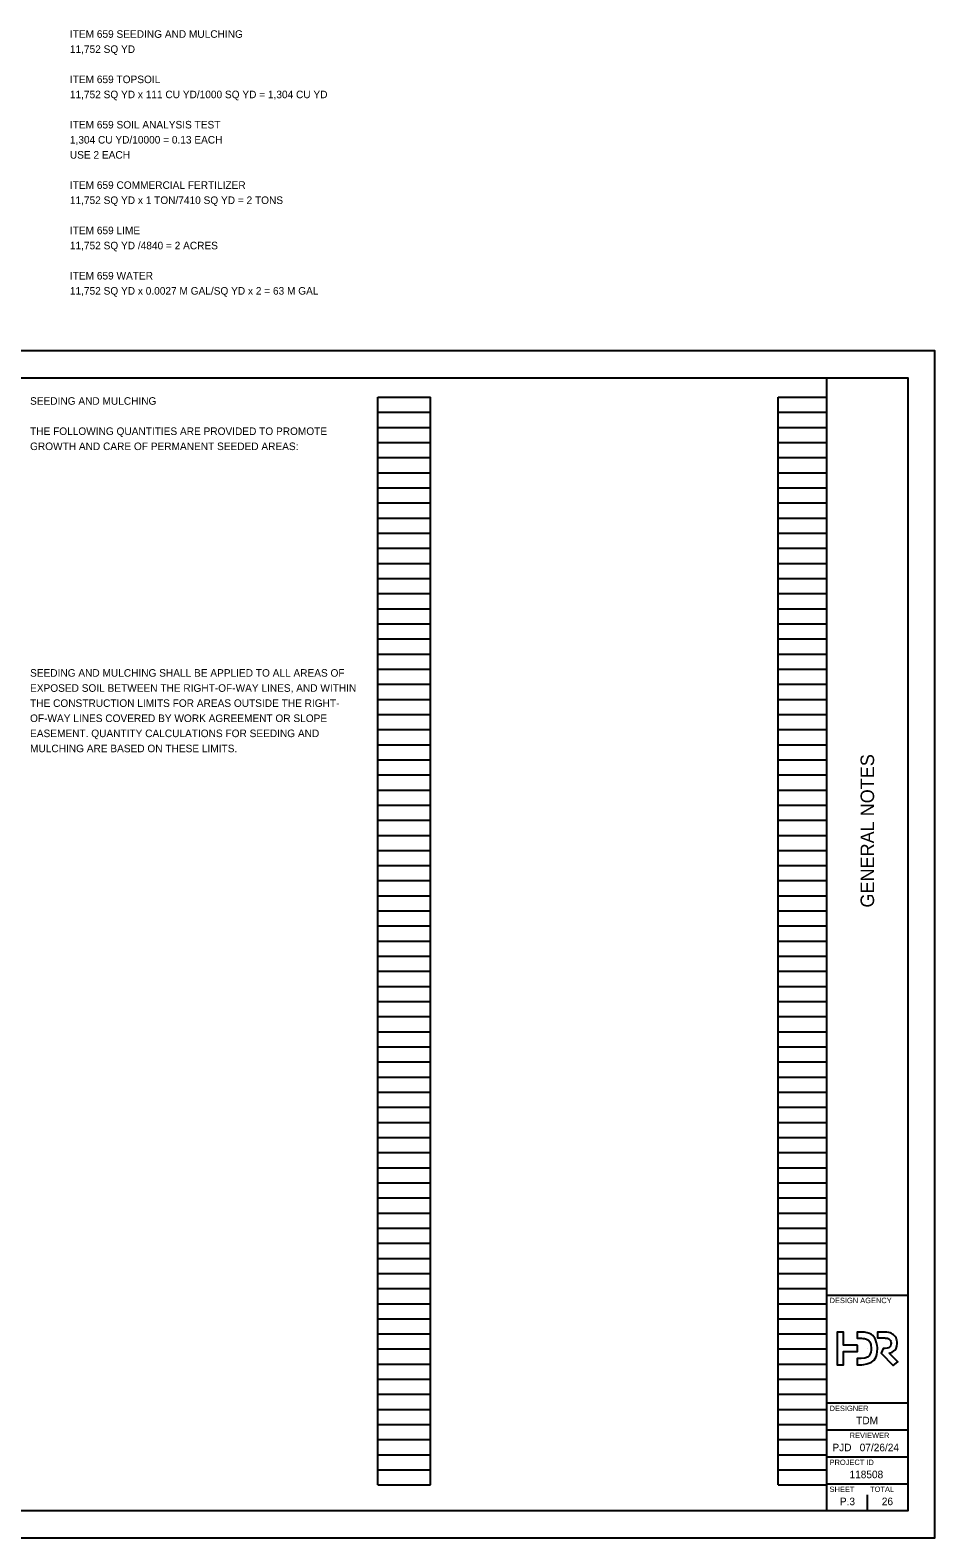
# Model space of a CAD drawing. Extents: x 0 to 34, y 0 to 27.9.
# Drawn here: x 17.24 to 34, y 0 to 27.94 of the extents above; entities that cross this region are included whole.
import ezdxf

# ---------------------------------------------------------------- set-up
doc = ezdxf.new("R2010")
doc.units = 0
for name, color, linetype in [('SH_Border', 7, 'Continuous'), ('SH_Cut_Line', 7, 'Continuous'), ('SH_Data', 7, 'Continuous'), ('SH_Text', 7, 'Continuous')]:
    doc.layers.add(name, color=color, linetype=linetype)

msp = doc.modelspace()

# ---------------------------------------------------------------- linework, layer by layer
at = {"layer": 'SH_Border'}
for p, q in [((32, 0.5), (32, 21.5)), ((32, 4.5), (33.5, 4.5)), ((32, 2.5), (33.5, 2.5)), ((32, 2), (33.5, 2)), ((32, 1.5), (33.5, 1.5)), ((32, 1), (33.5, 1))]:
    msp.add_line(p, q, dxfattribs=at)
msp.add_lwpolyline([(1.5, 21.5), (33.5, 21.5), (33.5, 0.5), (1.5, 0.5)], close=True, dxfattribs=at)
at = {"layer": 'SH_Cut_Line'}
msp.add_lwpolyline([(0, 0), (34, 0), (34, 22), (0, 22)], close=True, dxfattribs=at)
at = {"layer": 'SH_Data'}
for p, q in [((23.68, 0.98), (23.68, 21.14)), ((23.68, 21.14), (24.66, 21.14)), ((24.66, 0.98), (24.66, 21.14)), ((31.1, 0.98), (31.1, 21.14)), ((31.1, 21.14), (32, 21.14)), ((32, 0.98), (32, 21.14)), ((23.68, 20.86), (24.66, 20.86)), ((31.1, 20.86), (32, 20.86)), ((23.68, 20.58), (24.66, 20.58)), ((31.1, 20.58), (32, 20.58)), ((23.68, 20.3), (24.66, 20.3)), ((31.1, 20.3), (32, 20.3)), ((23.68, 20.02), (24.66, 20.02)), ((31.1, 20.02), (32, 20.02)), ((23.68, 19.74), (24.66, 19.74)), ((31.1, 19.74), (32, 19.74)), ((23.68, 19.46), (24.66, 19.46)), ((31.1, 19.46), (32, 19.46)), ((23.68, 19.18), (24.66, 19.18)), ((31.1, 19.18), (32, 19.18)), ((23.68, 18.9), (24.66, 18.9)), ((31.1, 18.9), (32, 18.9)), ((23.68, 18.62), (24.66, 18.62)), ((31.1, 18.62), (32, 18.62)), ((23.68, 18.34), (24.66, 18.34)), ((31.1, 18.34), (32, 18.34)), ((23.68, 18.06), (24.66, 18.06)), ((31.1, 18.06), (32, 18.06)), ((23.68, 17.78), (24.66, 17.78)), ((31.1, 17.78), (32, 17.78)), ((23.68, 17.5), (24.66, 17.5)), ((31.1, 17.5), (32, 17.5)), ((23.68, 17.22), (24.66, 17.22)), ((31.1, 17.22), (32, 17.22)), ((23.68, 16.94), (24.66, 16.94)), ((31.1, 16.94), (32, 16.94)), ((23.68, 16.66), (24.66, 16.66)), ((31.1, 16.66), (32, 16.66)), ((23.68, 16.38), (24.66, 16.38)), ((31.1, 16.38), (32, 16.38)), ((23.68, 16.1), (24.66, 16.1)), ((31.1, 16.1), (32, 16.1)), ((23.68, 15.82), (24.66, 15.82)), ((31.1, 15.82), (32, 15.82)), ((23.68, 15.54), (24.66, 15.54)), ((31.1, 15.54), (32, 15.54)), ((23.68, 15.26), (24.66, 15.26)), ((31.1, 15.26), (32, 15.26)), ((23.68, 14.98), (24.66, 14.98)), ((31.1, 14.98), (32, 14.98)), ((23.68, 14.7), (24.66, 14.7)), ((31.1, 14.7), (32, 14.7)), ((23.68, 14.42), (24.66, 14.42)), ((31.1, 14.42), (32, 14.42)), ((23.68, 14.14), (24.66, 14.14)), ((31.1, 14.14), (32, 14.14)), ((23.68, 13.86), (24.66, 13.86)), ((31.1, 13.86), (32, 13.86)), ((23.68, 13.58), (24.66, 13.58)), ((31.1, 13.58), (32, 13.58)), ((23.68, 13.3), (24.66, 13.3)), ((31.1, 13.3), (32, 13.3)), ((23.68, 13.02), (24.66, 13.02)), ((31.1, 13.02), (32, 13.02)), ((23.68, 12.74), (24.66, 12.74)), ((31.1, 12.74), (32, 12.74)), ((23.68, 12.46), (24.66, 12.46)), ((31.1, 12.46), (32, 12.46)), ((23.68, 12.18), (24.66, 12.18)), ((31.1, 12.18), (32, 12.18)), ((23.68, 11.9), (24.66, 11.9)), ((31.1, 11.9), (32, 11.9)), ((23.68, 11.62), (24.66, 11.62)), ((31.1, 11.62), (32, 11.62)), ((23.68, 11.34), (24.66, 11.34)), ((31.1, 11.34), (32, 11.34)), ((23.68, 11.06), (24.66, 11.06)), ((31.1, 11.06), (32, 11.06)), ((23.68, 10.78), (24.66, 10.78)), ((31.1, 10.78), (32, 10.78)), ((23.68, 10.5), (24.66, 10.5)), ((31.1, 10.5), (32, 10.5)), ((23.68, 10.22), (24.66, 10.22)), ((31.1, 10.22), (32, 10.22)), ((23.68, 9.94), (24.66, 9.94)), ((31.1, 9.94), (32, 9.94)), ((23.68, 9.66), (24.66, 9.66)), ((31.1, 9.66), (32, 9.66)), ((23.68, 9.38), (24.66, 9.38)), ((31.1, 9.38), (32, 9.38)), ((23.68, 9.1), (24.66, 9.1)), ((31.1, 9.1), (32, 9.1)), ((23.68, 8.82), (24.66, 8.82)), ((31.1, 8.82), (32, 8.82)), ((23.68, 8.54), (24.66, 8.54)), ((31.1, 8.54), (32, 8.54)), ((23.68, 8.26), (24.66, 8.26)), ((31.1, 8.26), (32, 8.26)), ((23.68, 7.98), (24.66, 7.98)), ((31.1, 7.98), (32, 7.98)), ((23.68, 7.7), (24.66, 7.7)), ((31.1, 7.7), (32, 7.7)), ((23.68, 7.42), (24.66, 7.42)), ((31.1, 7.42), (32, 7.42)), ((23.68, 7.14), (24.66, 7.14)), ((31.1, 7.14), (32, 7.14)), ((23.68, 6.86), (24.66, 6.86)), ((31.1, 6.86), (32, 6.86)), ((23.68, 6.58), (24.66, 6.58)), ((31.1, 6.58), (32, 6.58)), ((23.68, 6.3), (24.66, 6.3)), ((31.1, 6.3), (32, 6.3)), ((23.68, 6.02), (24.66, 6.02)), ((31.1, 6.02), (32, 6.02)), ((23.68, 5.74), (24.66, 5.74)), ((31.1, 5.74), (32, 5.74)), ((23.68, 5.46), (24.66, 5.46)), ((31.1, 5.46), (32, 5.46)), ((23.68, 5.18), (24.66, 5.18)), ((31.1, 5.18), (32, 5.18)), ((23.68, 4.9), (24.66, 4.9)), ((31.1, 4.9), (32, 4.9)), ((23.68, 4.62), (24.66, 4.62)), ((31.1, 4.62), (32, 4.62)), ((23.68, 4.34), (24.66, 4.34)), ((31.1, 4.34), (32, 4.34)), ((23.68, 4.06), (24.66, 4.06)), ((31.1, 4.06), (32, 4.06)), ((23.68, 3.78), (24.66, 3.78)), ((31.1, 3.78), (32, 3.78)), ((23.68, 3.5), (24.66, 3.5)), ((31.1, 3.5), (32, 3.5)), ((32.75, 3.5), (32.75, 3.5)), ((23.68, 3.22), (24.66, 3.22)), ((31.1, 3.22), (32, 3.22)), ((23.68, 2.94), (24.66, 2.94)), ((31.1, 2.94), (32, 2.94)), ((23.68, 2.66), (24.66, 2.66)), ((31.1, 2.66), (32, 2.66)), ((23.68, 2.38), (24.66, 2.38)), ((31.1, 2.38), (32, 2.38)), ((23.68, 2.1), (24.66, 2.1)), ((31.1, 2.1), (32, 2.1)), ((23.68, 1.82), (24.66, 1.82)), ((31.1, 1.82), (32, 1.82)), ((23.68, 1.54), (24.66, 1.54)), ((31.1, 1.54), (32, 1.54)), ((23.68, 1.26), (24.66, 1.26)), ((31.1, 1.26), (32, 1.26)), ((23.68, 0.98), (24.66, 0.98)), ((31.1, 0.98), (32, 0.98)), ((32.375, 0.675), (32.375, 0.675)), ((32.75, 0.5), (32.75, 0.8))]:
    msp.add_line(p, q, dxfattribs=at)
msp.add_lwpolyline([(32.565, 3.571), (32.311, 3.571), (32.311, 3.813), (32.189, 3.813), (32.189, 3.209), (32.311, 3.209), (32.311, 3.451), (32.565, 3.451)], close=True, dxfattribs=at)
for points in [[(32.634, 3.813), (32.562, 3.813), (32.562, 3.7), (32.634, 3.7)], [(33.063, 3.813), (32.935, 3.813), (32.935, 3.704), (33.072, 3.704)], [(32.936, 3.511), (32.936, 3.511), (32.936, 3.511), (32.936, 3.512), (32.936, 3.512)], [(33.077, 3.51), (33.043, 3.51), (33.003, 3.424), (33.226, 3.192), (33.313, 3.265), (33.155, 3.425)], [(32.634, 3.322), (32.562, 3.322), (32.562, 3.209), (32.634, 3.209)]]:
    msp.add_lwpolyline(points, dxfattribs=at)
for points in [[(32.936, 3.512), (32.936, 3.512), (32.935, 3.686), (32.808, 3.813), (32.634, 3.813)], [(32.634, 3.7), (32.634, 3.7), (32.744, 3.7), (32.822, 3.622), (32.822, 3.511)], [(33.239, 3.759), (33.239, 3.759), (33.193, 3.802), (33.141, 3.813), (33.063, 3.813)], [(33.072, 3.704), (33.072, 3.704), (33.113, 3.704), (33.141, 3.696), (33.161, 3.676)], [(33.161, 3.676), (33.161, 3.676), (33.179, 3.658), (33.189, 3.634), (33.189, 3.607)], [(33.302, 3.605), (33.302, 3.605), (33.302, 3.668), (33.284, 3.716), (33.239, 3.759)], [(32.822, 3.511), (32.822, 3.511), (32.822, 3.4), (32.744, 3.322), (32.634, 3.322)], [(32.634, 3.209), (32.634, 3.209), (32.808, 3.209), (32.935, 3.336), (32.936, 3.511)], [(33.189, 3.607), (33.189, 3.607), (33.189, 3.546), (33.136, 3.51), (33.077, 3.51)], [(33.155, 3.425), (33.155, 3.425), (33.242, 3.441), (33.302, 3.521), (33.302, 3.605)]]:
    msp.add_open_spline(points, degree=3, dxfattribs=at)

# ---------------------------------------------------------------- texts
msp.add_text('GENERAL NOTES', height=0.25, rotation=90, dxfattribs=at).set_placement((32.875, 11.682))
for s, height, p in [('DESIGN AGENCY', 0.1, (32.05, 4.35)), ('DESIGNER', 0.1, (32.05, 2.35)), ('TDM', 0.14, (32.543, 2.105)), ('PJD', 0.14, (32.103, 1.605)), ('REVIEWER', 0.1, (32.422, 1.85)), ('07/26/24', 0.14, (32.608, 1.605)), ('PROJECT ID', 0.1, (32.05, 1.35)), ('118508', 0.14, (32.419, 1.105)), ('SHEET', 0.1, (32.05, 0.85)), ('TOTAL', 0.1, (32.8, 0.85)), ('P.3', 0.14, (32.241, 0.605)), ('26', 0.14, (33.018, 0.605))]:
    msp.add_text(s, height=height, dxfattribs=at).set_placement(p)
at = {"layer": 'SH_Text'}
for s, p in [('ITEM 659 SEEDING AND MULCHING', (17.978, 27.801)), ('11,752 SQ YD', (17.978, 27.521)), ('11,752 SQ YD x 111 CU YD/1000 SQ YD = 1,304 CU YD', (17.978, 26.681)), ('ITEM 659 TOPSOIL', (17.978, 26.961)), ('1,304 CU YD/10000 = 0.13 EACH', (17.978, 25.841)), ('ITEM 659 SOIL ANALYSIS TEST', (17.978, 26.121)), ('USE 2 EACH', (17.978, 25.561)), ('ITEM 659 COMMERCIAL FERTILIZER', (17.978, 25.001)), ('11,752 SQ YD x 1 TON/7410 SQ YD = 2 TONS', (17.978, 24.721)), ('ITEM 659 LIME', (17.978, 24.161)), ('11,752 SQ YD /4840 = 2 ACRES', (17.978, 23.881)), ('ITEM 659 WATER', (17.978, 23.321)), ('11,752 SQ YD x 0.0027 M GAL/SQ YD x 2 = 63 M GAL', (17.978, 23.041)), ('SEEDING AND MULCHING', (17.24, 21)), ('THE FOLLOWING QUANTITIES ARE PROVIDED TO PROMOTE', (17.24, 20.44)), ('GROWTH AND CARE OF PERMANENT SEEDED AREAS:', (17.24, 20.16)), ('SEEDING AND MULCHING SHALL BE APPLIED TO ALL AREAS OF', (17.24, 15.96)), ('EXPOSED SOIL BETWEEN THE RIGHT-OF-WAY LINES, AND WITHIN', (17.24, 15.68)), ('THE CONSTRUCTION LIMITS FOR AREAS OUTSIDE THE RIGHT-', (17.24, 15.4)), ('OF-WAY LINES COVERED BY WORK AGREEMENT OR SLOPE', (17.24, 15.12)), ('EASEMENT. QUANTITY CALCULATIONS FOR SEEDING AND', (17.24, 14.84)), ('MULCHING ARE BASED ON THESE LIMITS.', (17.24, 14.56))]:
    msp.add_text(s, height=0.14, dxfattribs=at).set_placement(p)

doc.saveas('drawing.dxf')
